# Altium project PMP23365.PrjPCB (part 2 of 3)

## Sheet PMP23365B_SH2.SchDoc: Active Clamp Forward Converter
size 558 x 431 mm; Date: Not shown in title block; ApprovedBy: Not shown in title block; CheckedBy: Not shown in title block; Author: Not shown in title block; CompanyName: Not shown in title block; DrawnBy: D Xing; Engineer: Not shown in title block; Organization: Not shown in title block; Address1: Not shown in title block; Address2: Not shown in title block; Address3: Not shown in title block; Address4: Not shown in title block; DocumentNumber: 1; Revision: Use project parameter SCH_Rev; SheetNumber: 2; SheetTotal: 3; PageSetup: Record=PageOptions¦CenterHorizontal=True¦CenterVertical=True¦PrintScale=1.00¦XCorrection=1.00¦YCorrection=1.00¦PrintKind=0¦BorderSize=5000000¦LeftOffset=0¦BottomOffset=0¦Orientation=2¦PaperLength=1000¦PaperWidth=1000¦Scale=100¦PaperSource=15¦PrintQuality=600¦MediaType=1¦DitherType=10¦PaperKind=Letter¦PrintScaleMode=1
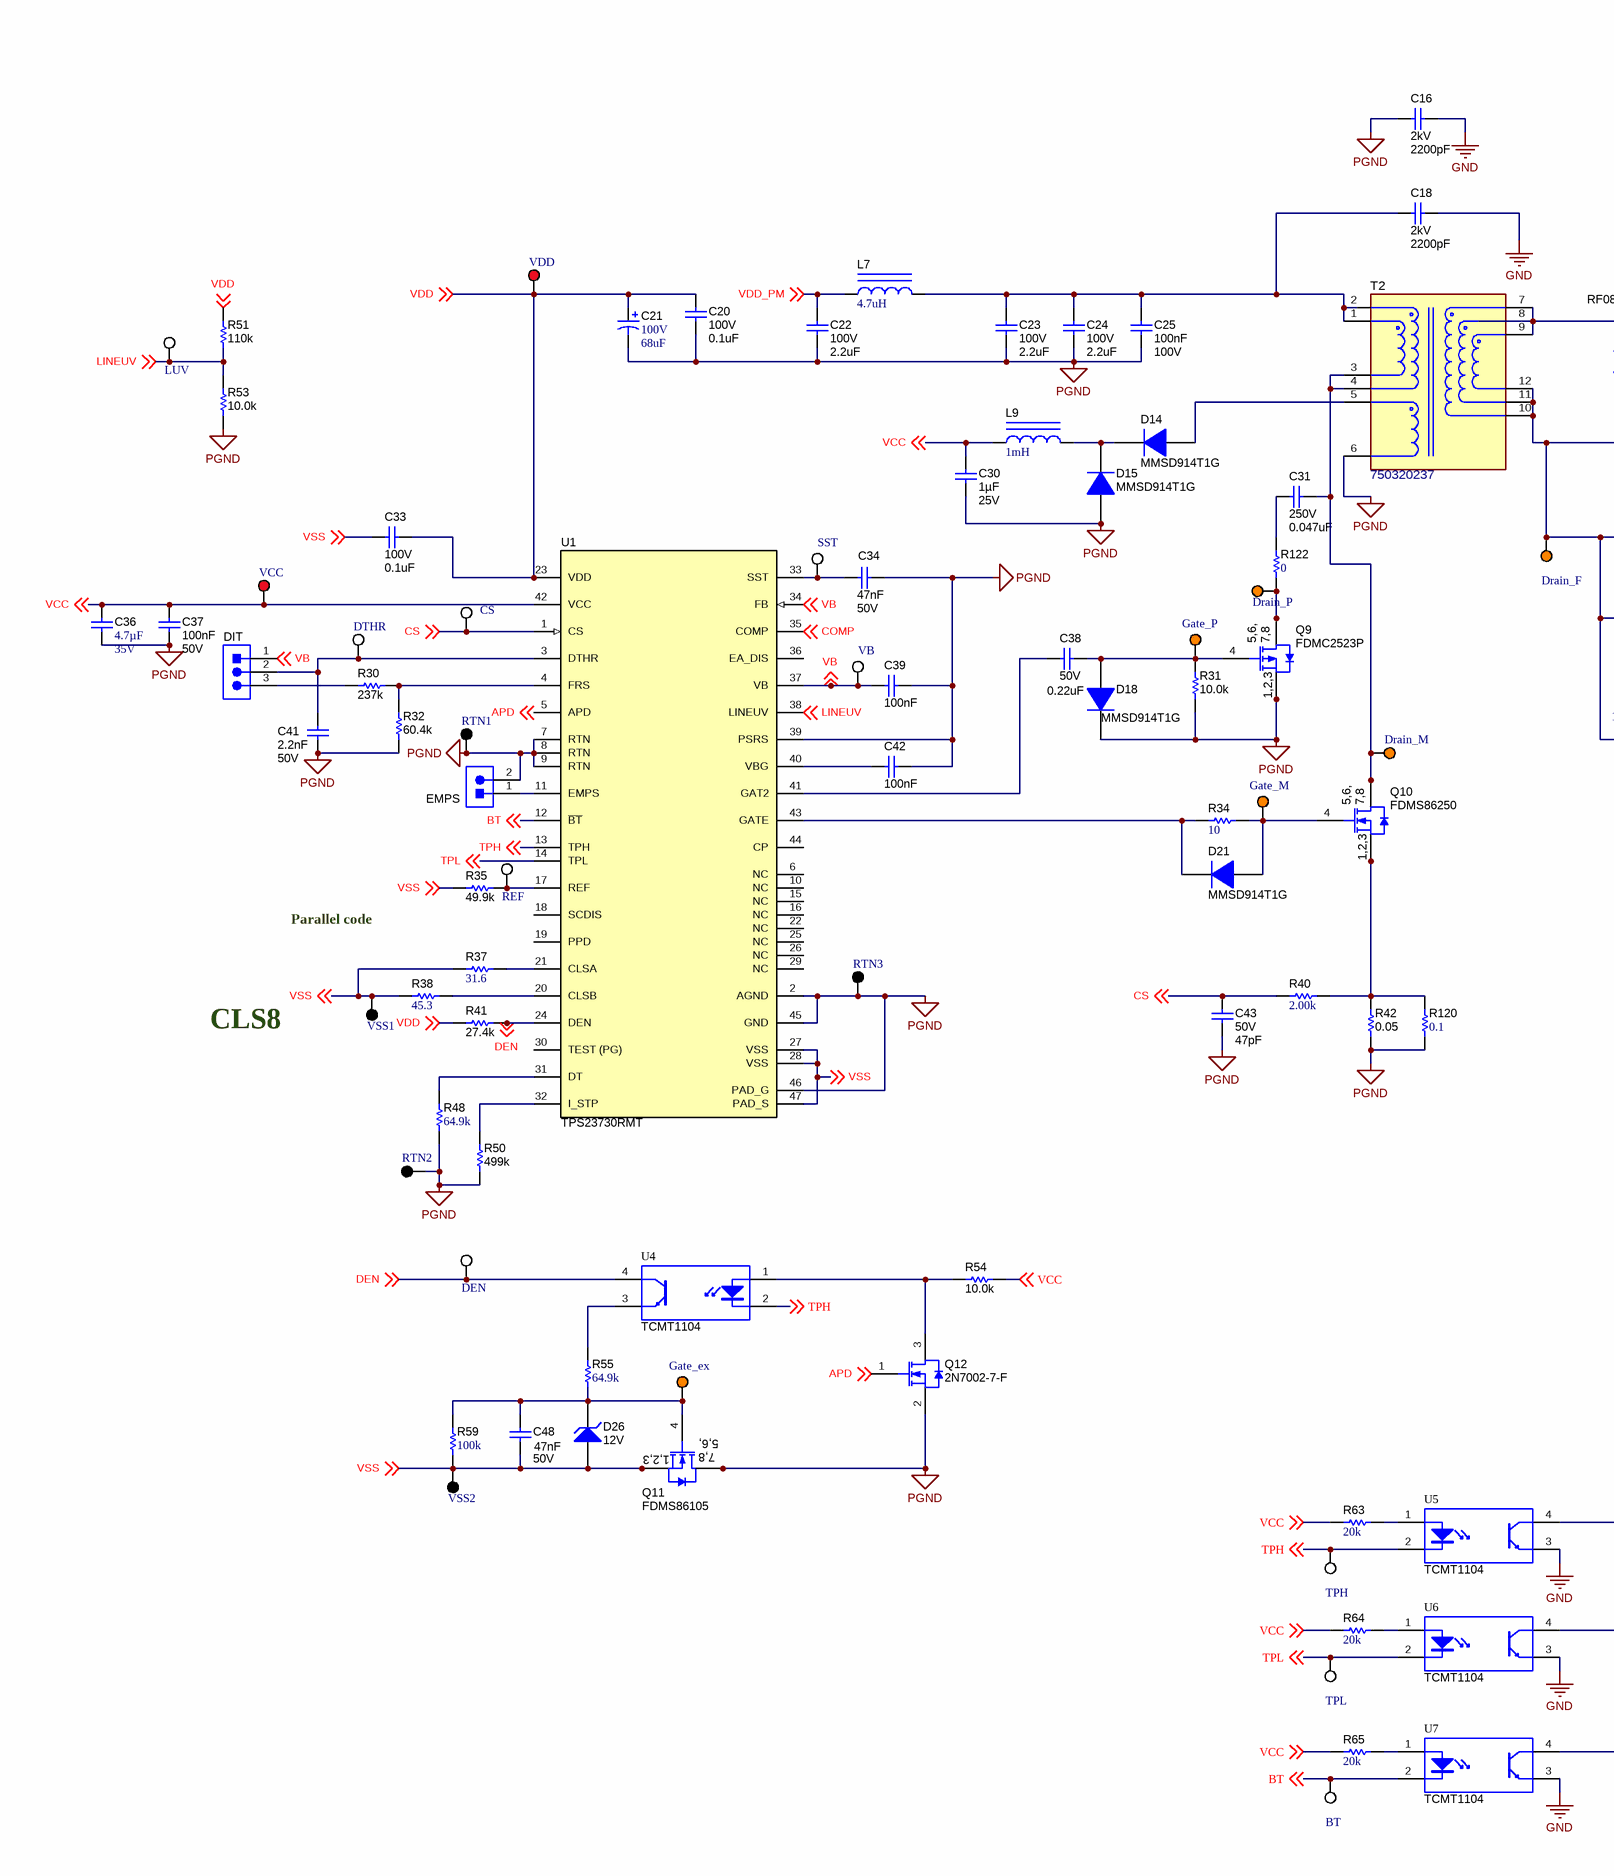
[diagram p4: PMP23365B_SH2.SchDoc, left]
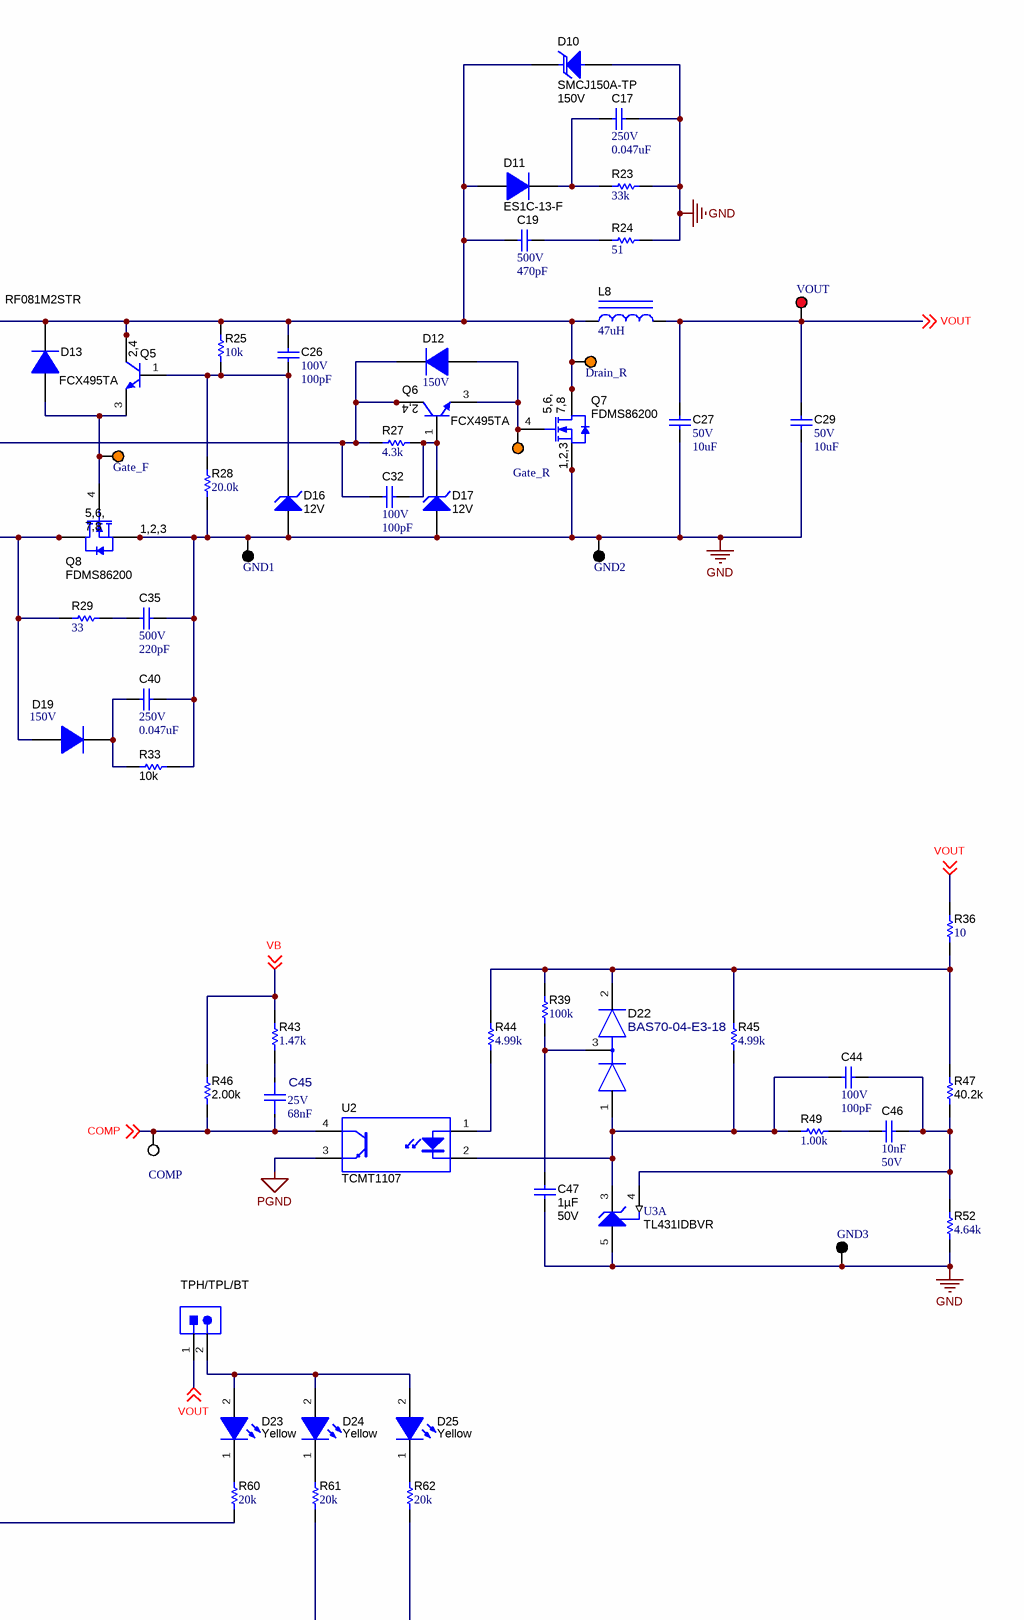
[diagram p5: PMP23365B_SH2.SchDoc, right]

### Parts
BT  5002  [Keystone5002]  (value not drawn)
C16  VDC_V: 2kV  ValueDisplayed: 2200pF  [1812_HV]  (hidden comment: C4532X7R3D222K130KA)
C17  VDC_V: 250V  ValueDisplayed: 0.047uF  [1206_180]  (hidden comment: GRM31CR72E473KW03L)
C18  VDC_V: 2kV  ValueDisplayed: 2200pF  [1812_HV]  (hidden comment: C4532X7R3D222K130KA)
C19  VDC_V: 500V  ValueDisplayed: 470pF  [1206]  (hidden comment: VJ1206Y471KBEAT4X)
C20  VDC_V: 100V  ValueDisplayed: 0.1uF  [1206]  (hidden comment: GRM319R72A104KA01D)
C21  VDC_V: 100V  ValueDisplayed: 68uF  [CAPSMT_62_KE0]  (hidden comment: EMVA101ATR680MKE0S)
C22  VDC_V: 100V  ValueDisplayed: 2.2uF  [1210_270]  (hidden comment: GRM32ER72A225KA35L)
C23  VDC_V: 100V  ValueDisplayed: 2.2uF  [1210_270]  (hidden comment: GRM32ER72A225KA35L)
C24  VDC_V: 100V  ValueDisplayed: 2.2uF  [1210_270]  (hidden comment: GRM32ER72A225KA35L)
C25  Cap_F: 100nF  VDC_V: 100V  [0805_HV]  (hidden comment: GRM21BR72A104KAC4L)
C26  VDC_V: 100V  ValueDisplayed: 100pF  [0603]  (hidden comment: GCM1885C2A101JA16D)
C27  VDC_V: 50V  ValueDisplayed: 10uF  [1210_270]  (hidden comment: GRM32ER61H106KA12L)
C29  VDC_V: 50V  ValueDisplayed: 10uF  [1210_270]  (hidden comment: GRM32ER61H106KA12L)
C30  Cap_F: 1µF  VDC_V: 25V  [0805_HV]  (hidden comment: GRM21BR71E105KA99L)
C31  VDC_V: 250V  ValueDisplayed: 0.047uF  [1206_180]  (hidden comment: GRM31CR72E473KW03L)
C32  VDC_V: 100V  ValueDisplayed: 100pF  [0603]  (hidden comment: GCM1885C2A101JA16D)
C33  VDC_V: 100V  ValueDisplayed: 0.1uF  [1206]  (hidden comment: GRM319R72A104KA01D)
C34  Cap_F: 47nF  VDC_V: 50V  [0603]  (hidden comment: GRM188R71H473KA61D)
C35  VDC_V: 500V  ValueDisplayed: 220pF  [1206]  (hidden comment: VJ1206Y221KXEAT5Z)
C36  Cap_F: 4.7µF  VDC_V: 35V  [0805_HV]  (hidden comment: C2012X7R1V475K125AC)
C37  Cap_F: 100nF  VDC_V: 50V  [0805_HV]  (hidden comment: GCM21BR71H104KA37K)
C38  VDC_V: 50V  ValueDisplayed: 0.22uF  [0805_HV]  (hidden comment: C2012X5R1H224K125AA)
C39  Cap_F: 100nF  [0603]  (hidden comment: CGA3E2X7R1E104K080AA)
C40  VDC_V: 250V  ValueDisplayed: 0.047uF  [1206_180]  (hidden comment: GRM31CR72E473KW03L)
C41  Cap_F: 2.2nF  VDC_V: 50V  [0603]  (hidden comment: C0603C222K5RAC)
C42  Cap_F: 100nF  [0603]  (hidden comment: CGA3E2X7R1E104K080AA)
C43  VDC_V: 50V  ValueDisplayed: 47pF  [0603]  (hidden comment: GRM1885C1H470JA01D)
C44  VDC_V: 100V  ValueDisplayed: 100pF  [0603]  (hidden comment: GCM1885C2A101JA16D)
C45  VDC_V: 25V  ValueDisplayed: 68nF  [FP-C1608X8R1E683M080AA_0603-MFG]  (hidden comment: C1608X8R1E683M080AA)
C46  Cap_F: 10nF  VDC_V: 50V  [0603]  (hidden comment: C0603X103K5RACTU)
C47  Cap_F: 1µF  VDC_V: 50V  [0805_HV]  (hidden comment: C2012X7R1H105K125AB)
C48  Cap_F: 47nF  VDC_V: 50V  [0603]  (hidden comment: GRM188R71H473KA61D)
COMP  5002  [Keystone5002]  (value not drawn)
CS  5002  [Keystone5002]  (value not drawn)
D10  SMCJ150A-TP  value 150V  [SMC]
D11  ES1C-13-F  [SMA]
D12  value 150V  [SMA]  (hidden comment: ES1C-13-F)
D13  RF081M2STR  [SOD-123]
D14  MMSD914T1G  [SOD-123]
D15  MMSD914T1G  [SOD-123]
D16  value 12V  [SOD-123]  (hidden comment: MMSZ5242B-7-F)
D17  value 12V  [SOD-123]  (hidden comment: MMSZ5242B-7-F)
D18  MMSD914T1G  [SOD-123]
D19  value 150V  [SMA]  (hidden comment: ES1C-13-F)
D21  MMSD914T1G  [SOD-123]
D22  BAS70-04-E3-18  [FP-BAS70-04-E3-18_SOT23-3-MFG]
D23  value Yellow  [WL-SMCW_YELLOW]  (hidden comment: 150060YS75000)
D24  value Yellow  [WL-SMCW_YELLOW]  (hidden comment: 150060YS75000)
D25  value Yellow  [WL-SMCW_YELLOW]  (hidden comment: 150060YS75000)
D26  value 12V  [SOD-123]  (hidden comment: MMSZ5242B-7-F)
DEN  5002  [Keystone5002]  (value not drawn)
DIT  5-146278-3  [TE_5-146278-3]  (value not drawn)
Drain_F  5003  [Keystone5003]  (value not drawn)
Drain_M  5003  [Keystone5003]  (value not drawn)
Drain_P  5003  [Keystone5003]  (value not drawn)
Drain_R  5003  [Keystone5003]  (value not drawn)
DTHR  5002  [Keystone5002]  (value not drawn)
EMPS  5-146278-2  [TE_5-146278-2]  (value not drawn)
Gate_ex  5003  [Keystone5003]  (value not drawn)
Gate_F  5003  [Keystone5003]  (value not drawn)
Gate_M  5003  [Keystone5003]  (value not drawn)
Gate_P  5003  [Keystone5003]  (value not drawn)
Gate_R  5003  [Keystone5003]  (value not drawn)
GND1  5001  [Keystone5001]  (value not drawn)
GND2  5001  [Keystone5001]  (value not drawn)
GND3  5001  [Keystone5001]  (value not drawn)
L7  ValueDisplayed: 4.7uH  [IND_PIMB065T]  (hidden comment: PIMB065T-4R7)
L8  ValueDisplayed: 47uH  [WE-HCB_1890]  (hidden comment: 74435574700)
L9  ValueDisplayed: 1mH  [DO1608C]  (hidden comment: DO1608C-105MLB)
LUV  5002  [Keystone5002]  (value not drawn)
Q5  FCX495TA  [SOT-89-3]
Q6  FCX495TA  [SOT-89-3]
Q7  FDMS86200  [TRANS_Fairchild_PQFN08A]
Q8  FDMS86200  [TRANS_Fairchild_PQFN08A]
Q9  FDMC2523P  [MLP08S]
Q10  FDMS86250  [TRANS_Fairchild_PQFN08A]
Q11  FDMS86105  [PowerPAK_SO-8_NoVias]
Q12  2N7002-7-F  [SOT-23]
R23  ValueDisplayed: 33k  [2512]  (hidden comment: CRCW251233K0JNEG)
R24  ValueDisplayed: 51  [2512]  (hidden comment: CRCW251251R0JNEG)
R25  ValueDisplayed: 10k  [1206]  (hidden comment: CRCW120610K0JNEA)
R27  ValueDisplayed: 4.3k  [1206]  (hidden comment: CRCW12064K30JNEA)
R28  ValueDisplayed: 20.0k  [1206]  (hidden comment: CRCW120620K0FKEA)
R29  ValueDisplayed: 33  [1206]  (hidden comment: CRCW120633R0JNEA)
R30  ValueDisplayed: 237k  [0603]  (hidden comment: RC0603FR-07237KL)
R31  ValueDisplayed: 10.0k  [0603]  (hidden comment: CRCW060310K0FKEA)
R32  ValueDisplayed: 60.4k  [0603]  (hidden comment: CRCW060360K4FKEA)
R33  ValueDisplayed: 10k  [2512]  (hidden comment: CRCW251210K0JNEG)
R34  ValueDisplayed: 10  [0603]  (hidden comment: CRCW060310R0JNEA)
R35  ValueDisplayed: 49.9k  [0603]  (hidden comment: CRCW060349K9FKEA)
R36  ValueDisplayed: 10  [0603]  (hidden comment: CRCW060310R0JNEA)
R37  ValueDisplayed: 31.6  [0603]  (hidden comment: RC0603FR-0731R6L)
R38  ValueDisplayed: 45.3  [0603]  (hidden comment: RC0603FR-0745R3L)
R39  ValueDisplayed: 100k  [0603]  (hidden comment: CRCW0603100KJNEAC)
R40  ValueDisplayed: 2.00k  [0603]  (hidden comment: RC0603FR-072KL)
R41  ValueDisplayed: 27.4k  [0603]  (hidden comment: RC0603FR-0727K4L)
R42  ValueDisplayed: 0.05  [1206]  (hidden comment: ERJ-8CWFR050V)
R43  ValueDisplayed: 1.47k  [0603]  (hidden comment: RC0603FR-071K47L)
R44  ValueDisplayed: 4.99k  [0603]  (hidden comment: CRCW06034K99FKEA)
R45  ValueDisplayed: 4.99k  [0603]  (hidden comment: CRCW06034K99FKEA)
R46  ValueDisplayed: 2.00k  [0603]  (hidden comment: CRCW06032K00FKEA)
R47  ValueDisplayed: 40.2k  [0603]  (hidden comment: CRCW060340K2FKEA)
R48  ValueDisplayed: 64.9k  [0603]  (hidden comment: CRCW060364K9FKEA)
R49  ValueDisplayed: 1.00k  [0603]  (hidden comment: CRCW06031K00FKEA)
R50  ValueDisplayed: 499k  [0603]  (hidden comment: CRCW0603499KFKEA)
R51  ValueDisplayed: 110k  [0603]  (hidden comment: CRCW0603110KFKEA)
R52  ValueDisplayed: 4.64k  [0603]  (hidden comment: RC0603FR-074K64L)
R53  ValueDisplayed: 10.0k  [0603]  (hidden comment: CRCW060310K0FKEA)
R54  ValueDisplayed: 10.0k  [0603L]  (hidden comment: CRCW060310K0FKEA)
R55  ValueDisplayed: 64.9k  [0603]  (hidden comment: CRCW060364K9FKEA)
R59  ValueDisplayed: 100k  [0603]  (hidden comment: CRCW0603100KFKEA)
R60  ValueDisplayed: 20k  [0603]  (hidden comment: CRCW060320K0JNEA)
R61  ValueDisplayed: 20k  [0603]  (hidden comment: CRCW060320K0JNEA)
R62  ValueDisplayed: 20k  [0603]  (hidden comment: CRCW060320K0JNEA)
R63  ValueDisplayed: 20k  [0603]  (hidden comment: CRCW060320K0JNEA)
R64  ValueDisplayed: 20k  [0603]  (hidden comment: CRCW060320K0JNEA)
R65  ValueDisplayed: 20k  [0603]  (hidden comment: CRCW060320K0JNEA)
R120  ValueDisplayed: 0.1  [1206]  (hidden comment: CRM1206-FX-R100ELF)
R122  ValueDisplayed: 0  [0805_HV]  (hidden comment: MCR10EZPJ000)
REF  5002  [Keystone5002]  (value not drawn)
RTN1  5001  [Keystone5001]  (value not drawn)
RTN2  5001  [Keystone5001]  (value not drawn)
RTN3  5001  [Keystone5001]  (value not drawn)
SST  5002  [Keystone5002]  (value not drawn)
T2  750320237  [FP-750320237_SMT12_29MM65_21MM8-MFG]
TPH  5002  [Keystone5002]  (value not drawn)
TPH/TPL/BT  5-146278-2  [TE_5-146278-2]  (value not drawn)
TPL  5002  [Keystone5002]  (value not drawn)
U1  TPS23730RMT  [RMT0045A]
U2  TCMT1107  [SOP-4]
U3  TL431IDBVR  [DBV0005A_M]  (part A of 2)
U4  TCMT1104  [SOP-4]
U5  TCMT1104  [SOP-4]
U6  TCMT1104  [SOP-4]
U7  TCMT1104  [SOP-4]
VB  5002  [Keystone5002]  (value not drawn)
VCC  5000  [Keystone5000]  (value not drawn)
VDD  5000  [Keystone5000]  (value not drawn)
VOUT  5000  [Keystone5000]  (value not drawn)
VSS1  5001  [Keystone5001]  (value not drawn)
VSS2  5001  [Keystone5001]  (value not drawn)

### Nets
GND: C16.1 C17.1 C18.1 C27.2 C29.2 C35.1 C40.1 C47.2 D10.2(A) D16.2(A) D17.2(A) GND1.1 GND2.1 GND3.1 Q7.1(S) Q7.2(S) Q7.3(S) Q8.1(S) Q8.2(S) Q8.3(S) R23.2 R24.2 R28.1 R33.2 R52.1 U3.5(ANODE) U5.3(E) U6.3(E) U7.3(E)
PGND: C16.2 C20.2 C21.2(-) C22.2 C23.2 C24.2 C25.2 C30.2 C34.1 C36.2 C37.2 C39.1 C41.2 C42.1 C43.2 D15.2(A) D18.1(K) EMPS.2 Q9.1(S) Q9.2(S) Q9.3(S) Q11.5(D) Q11.6(D) Q11.7(D) Q11.8(D) Q11.9(D) Q12.2(S) R31.1 R32.1 R42.1 R48.2 R50.1 R53.1 R120.1 RTN1.1 RTN2.1 RTN3.1 T2.6 U1.2(AGND) U1.7(RTN) U1.8(RTN) U1.9(RTN) U1.39(PSRS) U1.45(GND) U1.46(PAD_G) U2.3(E)
APD: Q12.1(G) U1.5(APD) ; off-sheet APD
BT: BT.1 U1.12(~{BT}) U7.2(K) ; off-sheet BT
COMP: C45.1 COMP.1 R46.1 U1.35(COMP) U2.4(C) ; off-sheet COMP
CS: C43.1 CS.1 R40.1 U1.1(CS) ; off-sheet CS
DEN: DEN.1 R41.2 U1.24(DEN) U4.4(C) ; off-sheet DEN
LINEUV: LUV.1 R51.1 R53.2 U1.38(LINEUV) ; off-sheet LINEUV
TPH: TPH.1 U1.13(TPH) U4.2(K) U5.2(K) ; off-sheet TPH
TPL: TPL.1 U1.14(TPL) U6.2(K) ; off-sheet TPL
VB: C39.2 DIT.1 R43.2 R46.2 U1.34(FB) U1.37(VB) VB.1 ; off-sheet VB
VCC: C30.1 C36.1 C37.1 L9.1 R54.2 R63.2 R64.2 R65.2 U1.42(VCC) VCC.1 ; off-sheet VCC
VDD: C20.1 C21.1(+) C33.1 R41.1 R51.2 U1.23(VDD) VDD.1 ; off-sheet VDD
VDD_PM: C22.1 L7.1 ; off-sheet VDD_PM
VOUT: C27.1 C29.1 L8.2 R36.2 TPH/TPL/BT.1 VOUT.1 ; off-sheet VOUT
VSS: C33.2 C48.2 D26.2(A) Q11.1(S) Q11.2(S) Q11.3(S) R35.1 R37.1 R38.1 R59.1 U1.27(VSS) U1.28(VSS) U1.47(PAD_S) VSS1.1 VSS2.1 ; off-sheet VSS
NetC17_2: C17.2 D11.1(K) R23.1
NetC18_2: C18.2 C23.1 C24.1 C25.1 L7.2 T2.1 T2.2
NetC19_1: C19.1 R24.1
NetC19_2: C19.2 C26.2 D10.1(K) D11.2(A) D13.1(K) Drain_R.1 L8.1 Q5.2(C) Q5.4(C) Q7.5(D) Q7.6(D) Q7.7(D) Q7.8(D) R25.2 T2.7 T2.8 T2.9
NetC26_1: C26.1 D16.1(K) Q5.1(B) R25.1 R28.2
NetC31_1: C31.1 Drain_M.1 Q10.5(D) Q10.6(D) Q10.7(D) Q10.8(D) T2.3 T2.4
NetC31_2: C31.2 R122.2
NetC32_1: C32.1 D17.1(K) Q6.1(B) R27.1
NetC32_2: C32.2 D12.1(K) D19.2(A) Drain_F.1 Q6.2(C) Q6.4(C) Q8.5(D) Q8.6(D) Q8.7(D) Q8.8(D) R27.2 R29.1 T2.10 T2.11 T2.12
NetC34_2: C34.2 SST.1 U1.33(SST)
NetC35_2: C35.2 R29.2
NetC38_1: C38.1 D18.2(A) Gate_P.1 Q9.4(G) R31.2
NetC38_2: C38.2 U1.41(GAT2)
NetC40_2: C40.2 D19.1(K) R33.1
NetC41_1: C41.1 DIT.2 DTHR.1 U1.3(DTHR)
NetC42_2: C42.2 U1.40(VBG)
NetC44_1: C44.1 C46.1 R47.2 R52.2 U3.4(REF)
NetC44_2: C44.2 D22.1(1_ANODE) R45.1 R49.1 U2.2(K) U3.3(CATHODE)
NetC45_2: C45.2 R43.1
NetC46_2: C46.2 R49.2
NetC47_1: C47.1 D22.3(1_CATHODE/2_ANODE) R39.1
NetC48_1: C48.1 D26.1(K) Gate_ex.1 Q11.4(G) R55.2 R59.2
NetD12_2: D12.2(A) Gate_R.1 Q6.3(E) Q7.4(G)
NetD13_2: D13.2(A) Gate_F.1 Q5.3(E) Q8.4(G)
NetD14_1: D14.1(K) D15.1(K) L9.2
NetD14_2: D14.2(A) T2.5
NetD21_1: D21.1(K) R34.1 U1.43(GATE)
NetD21_2: D21.2(A) Gate_M.1 Q10.4(G) R34.2
NetD22_2: D22.2(2_CATHODE) R36.1 R39.2 R44.2 R45.2 R47.1
NetD23_1: D23.1(K) R60.2
NetD23_2: D23.2(A) D24.2(A) D25.2(A) TPH/TPL/BT.2
NetD24_1: D24.1(K) R61.2
NetD25_1: D25.1(K) R62.2
NetDIT_3: DIT.3 R30.1
NetDrain_P_1: Drain_P.1 Q9.5(D) Q9.6(D) Q9.7(D) Q9.8(D) R122.1
NetEMPS_1: EMPS.1 U1.11(EMPS)
NetQ10_1: Q10.1(S) Q10.2(S) Q10.3(S) R40.2 R42.2 R120.2
NetQ12_3: Q12.3(D) R54.1 U4.1(A)
NetR30_2: R30.2 R32.2 U1.4(FRS)
NetR35_2: R35.2 REF.1 U1.17(REF)
NetR37_2: R37.2 U1.21(CLSA)
NetR38_2: R38.2 U1.20(CLSB)
NetR44_1: R44.1 U2.1(A)
NetR48_1: R48.1 U1.31(DT)
NetR50_2: R50.2 U1.32(I_STP)
NetR55_1: R55.1 U4.3(E)
NetR60_1: R60.1 U5.4(C)
NetR61_1: R61.1 U6.4(C)
NetR62_1: R62.1 U7.4(C)
NetR63_1: R63.1 U5.1(A)
NetR64_1: R64.1 U6.1(A)
NetR65_1: R65.1 U7.1(A)

Not connected (* = marked no-connect by the designer): U1 6(NC) 10(NC) 15(NC) 16(NC) 18(SCDIS) 19(PPD) 22(NC) 25(NC) 26(NC) 29(NC) 30(TEST_(PG)) 36(EA_DIS) 44(CP)

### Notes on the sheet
- Parallel code
- CLS8

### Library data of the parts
BT DEN LUV REF TPH TPL = CMP-0055139-1: Test Point, Miniature, White, TH; Manufacturer: Keystone; CNHeader: FALSE; Green_Lifecycle: Active; Green_REACh: Passed; ContactFinish: Silver; CT: TRUE
C16 C18 = CMP-0009358-2: CAP, CERM, 2200 pF, 2000 V, +/- 10%, X7R, 1812; Manufacturer: TDK; TaMin_C: -55°C; Polarized: N; SizeAreaWB_mm2: 23.1; Value1: Unknown; U/M: EA; Value: 2200pF; TaMax_C: 125°C; SizeZ_mm: 1.35; SizeX_mm: 4.5; SizeY_mm: 3.2; Cap_Case: 1812; Value2: 2000V; SizeArea_mm2: 14.4; Cap_F: 2.2nF; AEC Category: Q200
C17 C31 C40 = CMP-0008975-2: CAP, CERM, 0.047 uF, 250 V, +/- 10%, X7R, 1206; Manufacturer: MuRata; TaMin_C: -55°C; Polarized: N; SizeAreaWB_mm2: 10.92; Value1: Unknown; U/M: EA; TaMax_C: 125°C; SizeZ_mm: 1.8; SizeX_mm: 3.2; SizeY_mm: 1.6; Cap_Case: 1206; SizeArea_mm2: 5.12; Cap_F: 47nF; AEC Category: Q200
C19 = CMP-0009053-2: CAP, CERM, 470 pF, 500 V, +/- 10%, X7R, 1206; Manufacturer: Vishay-Vitramon; TaMin_C: -55°C; Polarized: N; SizeAreaWB_mm2: 10.92; Value1: Unknown; U/M: EA; Value: 470pF; TaMax_C: 125°C; SizeZ_mm: 1.35; SizeX_mm: 3.2; SizeY_mm: 1.6; SizeArea_mm2: 5.12; AEC Category: Q200
C20 C33 = CMP-0008881-2: CAP, CERM, 0.1 uF, 100 V, +/- 10%, X7R, 1206; Manufacturer: MuRata; TaMin_C: -55°C; Polarized: N; SizeAreaWB_mm2: 10.92; Value1: Unknown; U/M: EA; Value: 0.1uF; TaMax_C: 125°C; SizeZ_mm: 1.35; SizeX_mm: 3.2; SizeY_mm: 1.6; SizeArea_mm2: 5.12; Cap_F: 100nF; AEC Category: Q200
C21 = CMP-0011231-3: CAP, AL, 68 uF, 100 V, +/- 20%, SMD; Manufacturer: Chemi-Con; TaMin_C: -40°C; Polarized: Y; SizeAreaWB_mm2: 225; Value1: Unknown; U/M: EA; Value: 68uF; TaMax_C: 85°C; SizeZ_mm: 13.5; SizeX_mm: 13; Cap_Case: KE0; SizeArea_mm2: 169; CompType: Capacitor; Cap_F: 68µF; IRMS_A: 380mA; AEC Category: Q200
C22-C24 = CMP-0009232-2: CAP, CERM, 2.2 uF, 100 V, +/- 10%, X7R, 1210; Manufacturer: MuRata; TaMin_C: -55°C; ESR_ohm: 7m; Polarized: N; SizeAreaWB_mm2: 14.7; Value1: 0.007 ohm; U/M: EA; Value: 2.2uF; TaMax_C: 125°C; SizeZ_mm: 2.7; SizeX_mm: 3.2; SizeY_mm: 2.5; Cap_Case: 1210; SizeArea_mm2: 8; Cap_F: 2.2µF; IRMS_A: 4.4A; AEC Category: Q200
C25 = CMP-0008363-2: CAP, CERM, 0.1 uF, 100 V, +/- 10%, X7R, 0805; Manufacturer: MuRata; TaMin_C: -55°C; Polarized: N; SizeAreaWB_mm2: 6.75; Value1: Unknown; U/M: EA; Value: 0.1uF; TaMax_C: 125°C; SizeZ_mm: 1.45; SizeX_mm: 2; SizeY_mm: 1.25; Cap_Case: 0805; SizeArea_mm2: 2.5; AEC Category: Q200
C26 C32 C44 = CMP-0007130-4: CAP, CERM, 100 pF, 100 V, +/- 5%, C0G/NP0, AEC-Q200 Grade 1, 0603; Manufacturer: MuRata; TaMin_C: -55°C; Polarized: N; SizeAreaWB_mm2: 4.68; Value1: Unknown; U/M: EA; TaMax_C: 125°C; SizeZ_mm: 1; SizeX_mm: 1.6; SizeY_mm: 0.8; SizeArea_mm2: 1.28; AEC Qualified: Y; AEC Category: Q200; Value: 100pF
C27 C29 = CMP-0009214-2: CAP, CERM, 10 uF, 50 V, +/- 10%, X5R, 1210; Manufacturer: MuRata; TaMin_C: -55°C; Polarized: N; SizeAreaWB_mm2: 14.7; Value1: Unknown; U/M: EA; Value: 10uF; TaMax_C: 85°C; SizeZ_mm: 2.7; SizeX_mm: 3.2; SizeY_mm: 2.5; Cap_Case: 1210; SizeArea_mm2: 8; Cap_F: 10µF; AEC Category: Q200
C30 = CMP-0008336-2: CAP, CERM, 1 uF, 25 V, +/- 10%, X7R, 0805; Manufacturer: MuRata; TaMin_C: -55°C; Polarized: N; SizeAreaWB_mm2: 6.75; Value1: Unknown; U/M: EA; Value: 1uF; TaMax_C: 125°C; SizeZ_mm: 1.45; SizeX_mm: 2; SizeY_mm: 1.25; Cap_Case: 0805; SizeArea_mm2: 2.5; AEC Category: Q200
C34 C48 = CMP-0007457-4: CAP, CERM, 0.047 uF, 50 V, +/- 10%, X7R, 0603; Manufacturer: MuRata; TaMin_C: -55°C; Polarized: N; SizeAreaWB_mm2: 4.68; Value1: Unknown; U/M: EA; TaMax_C: 125°C; SizeZ_mm: 1; SizeX_mm: 1.6; SizeY_mm: 0.8; SizeArea_mm2: 1.28; AEC Category: Q200
C35 = CMP-0009046-1: CAP, CERM, 220 pF, 500 V, +/- 10%, X7R, 1206; Manufacturer: Vishay-Vitramon; TaMin_C: -55°C; Polarized: N; SizeAreaWB_mm2: 10.92; Value1: Unknown; U/M: EA; Value: 220pF; TaMax_C: 125°C; SizeZ_mm: 1.35; SizeX_mm: 3.2; SizeY_mm: 1.6; SizeArea_mm2: 5.12; AEC Category: Q200
C36 = CMP-0007885-1: CAP, CERM, 4.7 uF, 35 V, +/- 10%, X7R, 0805; Manufacturer: TDK; TaMin_C: -55°C; ESR_ohm: 2.346m; Polarized: N; SizeAreaWB_mm2: 6.75; Value1: 0.002346 ohm; U/M: EA; Value: 4.7uF; TaMax_C: 125°C; SizeZ_mm: 1.45; SizeX_mm: 2; SizeY_mm: 1.25; Cap_Case: 0805; SizeArea_mm2: 2.5; IRMS_A: 4.2602A; AEC Category: Q200
C37 = CMP-0008021-2: CAP, CERM, 0.1 uF, 50 V, +/- 10%, X7R, AEC-Q200 Grade 1, 0805; Manufacturer: MuRata; TaMin_C: -55°C; Polarized: N; SizeAreaWB_mm2: 6.75; Value1: Unknown; U/M: EA; Value: 0.1uF; TaMax_C: 125°C; SizeZ_mm: 1.45; SizeX_mm: 2; SizeY_mm: 1.25; Cap_Case: 0805; SizeArea_mm2: 2.5; AEC Qualified: Y; AEC Grade: 1; AEC Category: Q200
C38 = CMP-0007835-2: CAP, CERM, 0.22 uF, 50 V, +/- 10%, X5R, 0805; Manufacturer: TDK; TaMin_C: -55°C; ESR_ohm: 0.016949; Polarized: N; SizeAreaWB_mm2: 6.75; Value1: 0.016949 ohm; U/M: EA; Value: 0.22uF; TaMax_C: 85°C; SizeZ_mm: 1.45; SizeX_mm: 2; Cap_Case: 0805; SizeArea_mm2: 2.5; Cap_F: 220nF; SizeY_mm: 1.25; IRMS_A: 1.59611A; AEC Category: Q200
C39 C42 = CMP-0007077-5: CAP, CERM, 0.1 uF, 25 V, +/- 10%, X7R, AEC-Q200 Grade 1, 0603; Manufacturer: TDK; TaMin_C: -55°C; Polarized: N; SizeAreaWB_mm2: 4.68; Value1: Unknown; U/M: EA; Value: 0.1uF; TaMax_C: 125°C; SizeZ_mm: 1; SizeX_mm: 1.6; SizeY_mm: 0.8; Value2: 25V; SizeArea_mm2: 1.28; AEC Qualified: Y; AEC Category: Q200
C41 = CMP-0006897-4: CAP, CERM, 2200 pF, 50 V, +/- 10%, X7R, 0603; Manufacturer: Kemet; TaMin_C: -55°C; Polarized: N; SizeAreaWB_mm2: 4.68; Value1: Unknown; U/M: EA; Value: 2200pF; TaMax_C: 125°C; SizeZ_mm: 1; SizeX_mm: 1.6; SizeY_mm: 0.8; SizeArea_mm2: 1.28; AEC Category: Q200
C43 = CMP-0007220-4: CAP, CERM, 47 pF, 50 V, +/- 5%, C0G/NP0, 0603; Manufacturer: MuRata; TaMin_C: -55°C; Polarized: N; SizeAreaWB_mm2: 4.68; Value1: Unknown; U/M: EA; Value: 47pF; TaMax_C: 125°C; SizeZ_mm: 1; SizeX_mm: 1.6; SizeY_mm: 0.8; SizeArea_mm2: 1.28; AEC Category: Q200
C45 = CMP-0094554-1: Multilayer Ceramic Capacitors 68nF ±20% 25V X8R SMD 0603; Manufacturer: TDK; TempCo: 0.15; AEC Qualified: No; Tolerance_%: 0.2%; Voltage: 50V; SizeZ_mm: 0.9mm
C46 = CMP-0006978-4: CAP, CERM, 0.01 uF, 50 V, +/- 10%, X7R, 0603; Manufacturer: Kemet; TaMin_C: -55°C; Polarized: N; SizeAreaWB_mm2: 4.68; Value1: Unknown; U/M: EA; Value: 0.01uF; TaMax_C: 125°C; SizeZ_mm: 1; SizeX_mm: 1.6; SizeY_mm: 0.8; SizeArea_mm2: 1.28; AEC Category: Q200
C47 = CMP-0007873-2: CAP, CERM, 1 uF, 50 V, +/- 10%, X7R, 0805; Manufacturer: TDK; TaMin_C: -55°C; ESR_ohm: 8.782m; Polarized: N; SizeAreaWB_mm2: 6.75; Value1: 0.008782 ohm; U/M: EA; Value: 1uF; TaMax_C: 125°C; SizeZ_mm: 1.45; SizeX_mm: 2; SizeY_mm: 1.25; Cap_Case: 0805; SizeArea_mm2: 2.5; IRMS_A: 2.20488A; AEC Category: Q200
COMP CS DTHR SST VB = CMP-0055139-2: Test Point, Miniature, White, TH; Manufacturer: Keystone Electronics; ContactFinish: Silver; Green_REACh: Passed; CT: TRUE; Green_Lifecycle: Active; CNHeader: FALSE
D10 = CMP-0005708-3: Diode, TVS, Uni, 150 V, 243 Vc, SMC; Manufacturer: Micro Commercial Components; SizeX_mm: 8.13; Vc: 243V; AEC Category: Q101; SizeY_mm: 6.22; SizeAreaWB_mm2: 83.2686; SizeZ_mm: 2.6; Ppk: 1.5kW; AEC Qualified: N; Ipp: 6.2A; Value1: 1500W; Vbr_Max: 185V; SizeArea_mm2: 50.5686; Vbr_Min: 167V
D11 = CMP-0029023-2: Diode, Superfast Rectifier, 150 V, 1 A, SMA; Manufacturer: Diodes Inc.; TJmax_C: 150°C; Vr_V: 150V; Value2: 0.92V; SizeX_mm: 5.59; Green_REACh: Incomplete; SizeAreaWB_mm2: 37.3428; Value: 150V; Vf_V: 920mV; Green_Lifecycle: Not Set; Value1: 1A; SizeZ_mm: 2.87; SizeArea_mm2: 16.3228; SizeY_mm: 2.92; AEC Category: Q101; RJC_CperW: 25
D12 D19 = CMP-0029023-2: Diode, Superfast Rectifier, 150 V, 1 A, SMA; Manufacturer: Diodes Inc.; SizeX_mm: 5.59; RJC_CperW: 25; Vf_V: 920mV; TJmax_C: 150°C; SizeAreaWB_mm2: 37.3428; Io_A: 1A; Green_REACh: Incomplete; SizeY_mm: 2.92; Green_Lifecycle: Not Set; SizeArea_mm2: 16.3228; AEC Category: Q101; SizeZ_mm: 2.87; Value2: 0.92V
D13 = CMP-0076993-2: Diode, Fast Rectifier, 200 V, 0.8 A, SOD-123; Manufacturer: Rohm; Value: 200V; AEC Category: Q101; SizeAreaWB_mm2: 13.095; Value1: 0.8A; SizeY_mm: 1.7; SizeZ_mm: 1.35; Green_REACh: Incomplete; Green_Lifecycle: Not Set; Io_A: 800mA; SizeX_mm: 3.85; SizeArea_mm2: 6.545; TJmax_C: 150°C; Vf_V: 950mV; Value2: 0.95V
D14 D15 D18 D21 = CMP-0076981-2: Diode, Switching, 100 V, 0.2 A, SOD-123; Manufacturer: ON Semiconductor; Value1: 0.2A; Io_A: 200mA; TJmax_C: 150°C; Green_REACh: Incomplete; SizeY_mm: 1.7; Green_Lifecycle: Not Set; Vr_V: 100V; Value: 100V; SizeZ_mm: 1.35; AEC Category: Q101; SizeAreaWB_mm2: 13.095; SizeX_mm: 3.85; SizeArea_mm2: 6.545
D16 D17 D26 = CMP-0005751-4: Diode, Zener, 12 V, 500 mW, SOD-123; Manufacturer: Diodes Inc.; RJA_CperW: 350; SizeZ_mm: 1.35; SizeAreaWB_mm2: 13.095; AEC Category: Q101; SizeArea_mm2: 6.545; Power_W: 500mW; Value1: 0.5W; SizeY_mm: 1.7; SizeX_mm: 3.85
D22 = CMP-0096356-1: Diode Array 1 Pair Series Connection Schottky 70 V 200mA (DC) Surface Mount TO-236-3, SC-59, SOT-23-3; Manufacturer: Vishay; ValueDisplayed: 1.5pF; Vf_V: 70V; TJmax_C: 125°C; AEC Qualified: No; Peak Reverse Current: 0.02uA; SizeZ_mm: 1.15mm; Max Surge Forward Current: 600mA
D23-D25 = CMP-0002892-3: LED, Yellow, SMD; Manufacturer: Wurth Elektronik; Value1: W; Vf_V: 2V; Type: AlInGaP; Io_A: 20mA
DIT = CMP-0054951-1: Header, 100mil, 3x1, Tin, TH; Manufacturer: TE Connectivity; CNHeader: TRUE; Green_Lifecycle: Active; Green_REACh: Passed; CT: FALSE
Drain_F Drain_M Drain_P Drain_R Gate_ex Gate_F Gate_M Gate_P Gate_R = CMP-0055140-1: Test Point, Miniature, Orange, TH; Manufacturer: Keystone; CNHeader: FALSE; Green_Lifecycle: Active; Green_REACh: Passed; ContactFinish: Silver; CT: TRUE
EMPS TPH/TPL/BT = CMP-0054952-1: Header, 100mil, 2x1, Tin, TH; Manufacturer: TE Connectivity; CNHeader: TRUE; Green_Lifecycle: Active; Green_REACh: Passed; CT: FALSE
GND1-GND3 RTN1-RTN3 VSS1 VSS2 = CMP-0055138-2: Test Point, Miniature, Black, TH; Manufacturer: Keystone Electronics; ContactFinish: Silver; CNHeader: FALSE; Green_Lifecycle: Active; Green_REACh: Passed; CT: TRUE
L7 = CMP-0059863-1: Inductor, Drum Core, Ferrite, 4.7 uH, 6.5 A, 0.023 ohm, SMD; Manufacturer: Cyntec; Isat: 7A @ % inductance drop; Irms: 6.5A @ C rise; Green_Lifecycle: Not Set; SizeAreaWB_mm2: 77.83; DCR_ohm: 23m; Green_REACh: Incomplete; Value: 4.7uH; Imax_A: 6.5A; SizeZ_mm: 5; SizeX_mm: 7.05; SizeY_mm: 6.6; SizeArea_mm2: 46.53; Ind_H: 4.7µH; AEC Category: Q200
L8 = CMP-0064480-2: Inductor, Shielded Drum Core, Ferrite, 47 uH, 6.8 A, 0.0335 ohm, SMD; Manufacturer: Wurth Elektronik; Isat: 7A @ 30% inductance drop; Irms: 6.8A @ 50C rise; Green_Lifecycle: Active; SizeAreaWB_mm2: 410.06; DCR_ohm: 33.5m; Green_REACh: Passed; Value: 47uH; Imax_A: 6.8A; SizeZ_mm: 9.2; SizeX_mm: 18.3; SizeY_mm: 18.2; SizeArea_mm2: 333.06; Ind_H: 47µH; AEC Category: Q200
L9 = CMP-0061681-2: Inductor, Drum Core, Ferrite, 1 mH, 0.1 A, 13.8 ohm, SMD; Manufacturer: Coilcraft; Isat: 0.1A @ 10% inductance drop; Irms: 0.15A @ 15C rise; Green_Lifecycle: Not Set; SizeAreaWB_mm2: 55.47; DCR_ohm: 13.8; Green_REACh: Incomplete; Value: 1mH; Imax_A: 100mA; SizeZ_mm: 2.92; SizeX_mm: 6.6; SizeY_mm: 4.45; Value2: 0.1A; SizeArea_mm2: 29.37; AEC Category: Q200
Q5 Q6 = CMP-0000510-2: Transistor, NPN, 150 V, 1 A, AEC-Q101, SOT-89; Manufacturer: Diodes Inc.; TaMax_C: 150°C; Value2: 300; Value1: 1 A; Vcesat1_V: 200mV; SizeX_mm: 4.1; SizeY_mm: 4.5; TaMin_C: -65°C; IcRated_A: 1A; CompType: BJT; SizeZ_mm: 1.5; AEC Qualified: Y; Value: 150 V; SizeArea_mm2: 18.45; NPN: 1; Vceo_V: 150V; PNP: 0; AEC Category: Q101; SizeAreaWB_mm2: 28.05; U/M: EA
Q7 Q8 = CMP-0001056-1: MOSFET, N-CH, 150 V, 35 A, PQFN08A; Alternate Manufacturer: None; Manufacturer: Fairchild Semiconductor; SizeZ_mm: 1.1; ChType: N; Value2: 33 nC; VdsMax_V: 150V; SizeX_mm: 5; SizeAreaWB_mm2: 56; SizeY_mm: 6; Vgs_V: 20V; QgTyp_nC: 33; Value: 150V; SizeArea_mm2: 30; AEC Category: Q101; IdsMax_A: 35A; U/M: EA
Q9 = CMP-0000056-3: MOSFET, P-CH, -150 V, -3 A, QFN-8; Alternate Manufacturer: None; Manufacturer: Fairchild Semiconductor; ChType: P; VdsMax_V: -150V; AEC Category: Q101; Value2: 6.2 nC; SizeAreaWB_mm2: 18.49; QgTyp_nC: 6.2; Value: -150V; SizeZ_mm: 0.8; ChMode: Enhancement; AEC Qualified: N; IdsMax_A: -3A; SizeX_mm: 3.3; SizeArea_mm2: 10.89; Vgs_V: -30V
Q10 = CMP-0001057-1: MOSFET, N-CH, 150 V, 6.7 A, PQFN08A; Alternate Manufacturer: None; Manufacturer: Fairchild Semiconductor; SizeZ_mm: 1.1; ChType: N; Value2: 36 nC; Value1: 0.02; VdsMax_V: 150V; SizeX_mm: 5; SizeY_mm: 6; Vgs_V: 4V; Value: 150V; Rdson45_ohm: 0.025; SizeArea_mm2: 30; AEC Category: Q101; IdsMax_A: 6.7A; SizeAreaWB_mm2: 56; U/M: EA; QgTyp_nC: 36
Q11 = CMP-0000985-1: MOSFET, N-CH, 100 V, 26 A, PowerPAK SO-8; Alternate Manufacturer: None; Manufacturer: Fairchild Semiconductor; SizeZ_mm: 1.12; ChType: N; Value2: 4.2 nC; Value1: 0.03; VdsMax_V: 100V; SizeX_mm: 5.99; SizeY_mm: 4.9; Vgs_V: 20V; Value: 100V; Rdson45_ohm: 34m; SizeArea_mm2: 29.351; AEC Category: Q101; IdsMax_A: 26A; SizeAreaWB_mm2: 55.131; U/M: EA; QgTyp_nC: 4.2
Q12 = CMP-0000769-1: MOSFET, N-CH, 60 V, 0.17 A, SOT-23; Alternate Manufacturer: None; Manufacturer: Diodes Inc.; SizeZ_mm: 1.1; ChType: N; Value2: 223 nC; Value1: 7; VdsMax_V: 60V; SizeX_mm: 2.5; SizeY_mm: 3; Vgs_V: 20V; Value: 60V; Rdson45_ohm: 7.5; AEC Category: Q101; IdsMax_A: 170mA; SizeAreaWB_mm2: 14; U/M: EA; QgTyp_nC: 223
R23 = CMP-0015944-1: RES, 33 k, 5%, 1 W, AEC-Q200 Grade 0, 2512; Manufacturer: Vishay-Dale; Power_W: 1W; TempCo: 200 ppm/C; Value_Code: 33k0; U/M: EA; Value: 33k; EIA_Code: E24; SizeX_mm: 6.3; SizeY_mm: 3.2; SizeZ_mm: 0.71; SizeArea_mm2: 20.16; AEC Qualified: Y; VDC_V: 500V; AEC Grade: 0; AEC Category: Q200
R24 = CMP-0015978-3: RES, 51, 5%, 1 W, AEC-Q200 Grade 0, 2512; Manufacturer: Vishay-Dale; Power_W: 1W; TempCo: 200 ppm/C; Value_Code: 51R0; Value: 51; EIA_Code: E24; SizeX_mm: 6.3; SizeY_mm: 3.2; SizeZ_mm: 0.71; SizeArea_mm2: 20.16; AEC Qualified: Y; VDC_V: 500V; AEC Grade: 0; AEC Category: Q200
R25 = CMP-0018576-1: RES, 10 k, 5%, 0.25 W, 1206; Manufacturer: Vishay-Dale; Power_W: 250mW; TempCo: 200 ppm/C; Value_Code: 10k0; U/M: EA; Value: 10k; EIA_Code: E24; SizeX_mm: 3.2; SizeY_mm: 1.6; SizeZ_mm: 1.35; Value2: 0.25W; SizeArea_mm2: 5.12; VDC_V: 200V; AEC Category: Q200
R27 = CMP-0018688-2: RES, 4.3 k, 5%, 0.25 W, 1206; Manufacturer: Vishay-Dale; Power_W: 250mW; TempCo: 200 ppm/C; Value_Code: 4k30; U/M: EA; Value: 4.3k; EIA_Code: E24; SizeX_mm: 3.2; SizeY_mm: 1.6; SizeZ_mm: 1.35; Value2: 0.25W; SizeArea_mm2: 5.12; VDC_V: 200V; AEC Category: Q200
R28 = CMP-0016779-2: RES, 20.0 k, 1%, 0.25 W, 1206; Manufacturer: Vishay-Dale; Power_W: 250mW; TempCo: 100 ppm/C; Value_Code: 20k0; U/M: EA; Value: 20.0k; EIA_Code: E96; Res_ohm: 20k; SizeX_mm: 3.2; SizeY_mm: 1.6; SizeZ_mm: 1.35; Value2: 0.25W; SizeArea_mm2: 5.12; VDC_V: 200V; AEC Category: Q200
R29 = CMP-0018659-1: RES, 33, 5%, 0.25 W, 1206; Manufacturer: Vishay-Dale; Power_W: 250mW; TempCo: 200 ppm/C; Value_Code: 33R0; U/M: EA; Value: 33; EIA_Code: E24; SizeX_mm: 3.2; SizeY_mm: 1.6; SizeZ_mm: 1.35; Value2: 0.25W; SizeArea_mm2: 5.12; VDC_V: 200V; AEC Category: Q200
R30 = CMP-0022931-4: RES, 237 k, 1%, 0.1 W, 0603; Manufacturer: Yageo; Power_W: 100mW; TempCo: 100 ppm/C; Value: 237k; EIA_Code: E96; SizeX_mm: 1.6; SizeY_mm: 0.8; SizeZ_mm: 1; Value2: 0.1W; SizeArea_mm2: 1.28; AEC Qualified: N; VDC_V: 75V; AEC Category: Q200; SizeAreaWB_mm2: 4.68
R31 R53 = CMP-0021998-4: RES, 10.0 k, 1%, 0.1 W, AEC-Q200 Grade 0, 0603; Manufacturer: Vishay-Dale; Power_W: 100mW; TempCo: 100 ppm/C; Value_Code: 10k0; Value: 10.0k; EIA_Code: E96; Res_ohm: 10k; SizeX_mm: 1.6; SizeY_mm: 0.8; SizeZ_mm: 1; Value2: 0.1W; SizeArea_mm2: 1.28; AEC Qualified: Y; VDC_V: 75V; AEC Category: Q200; AEC Grade: 0
R32 = CMP-0022532-4: RES, 60.4 k, 1%, 0.1 W, AEC-Q200 Grade 0, 0603; Manufacturer: Vishay-Dale; Power_W: 100mW; TempCo: 100 ppm/C; Value_Code: 60k4; Value: 60.4k; EIA_Code: E96; SizeX_mm: 1.6; SizeY_mm: 0.8; SizeZ_mm: 1; Value2: 0.1W; SizeArea_mm2: 1.28; AEC Qualified: Y; VDC_V: 75V; AEC Category: Q200; AEC Grade: 0
R33 = CMP-0015868-3: RES, 10 k, 5%, 1 W, AEC-Q200 Grade 0, 2512; Manufacturer: Vishay-Dale; Power_W: 1W; TempCo: 200 ppm/C; Value_Code: 10k0; Value: 10k; EIA_Code: E24; SizeX_mm: 6.3; SizeY_mm: 3.2; SizeZ_mm: 0.71; SizeArea_mm2: 20.16; AEC Qualified: Y; VDC_V: 500V; AEC Grade: 0; AEC Category: Q200
R34 R36 = CMP-0025703-4: RES, 10, 5%, 0.1 W, AEC-Q200 Grade 0, 0603; Manufacturer: Vishay-Dale; Power_W: 100mW; TempCo: 200 ppm/C; Value_Code: 10R0; Value: 10; EIA_Code: E24; SizeX_mm: 1.6; SizeY_mm: 0.8; SizeZ_mm: 1; Value2: 0.1W; SizeArea_mm2: 1.28; AEC Qualified: Y; VDC_V: 75V; AEC Category: Q200; AEC Grade: 0
R35 = CMP-0022447-4: RES, 49.9 k, 1%, 0.1 W, AEC-Q200 Grade 0, 0603; Manufacturer: Vishay-Dale; Power_W: 100mW; TempCo: 100 ppm/C; Value_Code: 49k9; Value: 49.9k; EIA_Code: E96; SizeX_mm: 1.6; SizeY_mm: 0.8; SizeZ_mm: 1; Value2: 0.1W; SizeArea_mm2: 1.28; AEC Qualified: Y; VDC_V: 75V; AEC Category: Q200; AEC Grade: 0
R37 = CMP-0023027-4: RES, 31.6, 1%, 0.1 W, 0603; Manufacturer: Yageo; Power_W: 100mW; TempCo: 100 ppm/C; Value_Code: 31R6; Value: 31.6; EIA_Code: E96; SizeX_mm: 1.6; SizeY_mm: 0.8; SizeZ_mm: 1; Value2: 0.1W; SizeArea_mm2: 1.28; AEC Qualified: N; VDC_V: 75V; AEC Category: Q200; SizeAreaWB_mm2: 4.68
R38 = CMP-0023123-5: RES, 45.3, 1%, 0.1 W, 0603; Manufacturer: Yageo; Power_W: 100mW; TempCo: 100 ppm/C; Value_Code: 45R3; Value: 45.3; EIA_Code: E96; SizeX_mm: 1.6; SizeY_mm: 0.8; SizeZ_mm: 1; Value2: 0.1W; SizeArea_mm2: 1.28; AEC Qualified: N; VDC_V: 75V; AEC Category: Q200; SizeAreaWB_mm2: 4.68
R39 = CMP-0082530-1: RES, 100 k, 5%, 0.1 W, 0603; Manufacturer: Vishay-Dale; Power_W: 100mW; TempCo: 200 ppm/C; SizeAreaWB_mm2: 4.68; Value: 100k; EIA_Code: E24; SizeX_mm: 1.6; SizeY_mm: 0.8; SizeZ_mm: 1; Value2: 0.1W; SizeArea_mm2: 1.28; AEC Qualified: N; VDC_V: 75V; AEC Category: Q200
R40 = CMP-0023000-5: RES, 2.00 k, 1%, 0.1 W, 0603; Manufacturer: Yageo; Power_W: 100mW; TempCo: 100 ppm/C; Value_Code: 2k00; Value: 2.00k; EIA_Code: E96; Res_ohm: 2k; SizeX_mm: 1.6; SizeY_mm: 0.8; SizeZ_mm: 1; Value2: 0.1W; SizeArea_mm2: 1.28; AEC Qualified: N; VDC_V: 75V; AEC Category: Q200; SizeAreaWB_mm2: 4.68
R41 = CMP-0022965-5: RES, 27.4 k, 1%, 0.1 W, 0603; Manufacturer: Yageo; Power_W: 100mW; TempCo: 100 ppm/C; Value_Code: 27k4; Value: 27.4k; EIA_Code: E96; SizeX_mm: 1.6; SizeY_mm: 0.8; SizeZ_mm: 1; Value2: 0.1W; SizeArea_mm2: 1.28; AEC Qualified: N; VDC_V: 75V; AEC Category: Q200; SizeAreaWB_mm2: 4.68
R42 = CMP-0017281-2: RES, 0.05, 1%, 1 W, AEC-Q200 Grade 0, 1206; Manufacturer: Panasonic; SizeZ_mm: 1.35; Value2: 1W; SizeArea_mm2: 5.12; AEC Qualified: Y; AEC Grade: 0; AEC Category: Q200; TempCo: 50 ppm/C; Value_Code: R050; U/M: EA; Value: 0.05; EIA_Code: E96; SizeX_mm: 3.2; SizeY_mm: 1.6
R43 = CMP-0022879-5: RES, 1.47 k, 1%, 0.1 W, 0603; Manufacturer: Yageo; Power_W: 100mW; TempCo: 100 ppm/C; Value_Code: 1k47; Value: 1.47k; EIA_Code: E96; SizeX_mm: 1.6; SizeY_mm: 0.8; SizeZ_mm: 1; Value2: 0.1W; SizeArea_mm2: 1.28; AEC Qualified: N; VDC_V: 75V; AEC Category: Q200; SizeAreaWB_mm2: 4.68
R44 R45 = CMP-0022458-2: RES, 4.99 k, 1%, 0.1 W, 0603; Manufacturer: Vishay-Dale; Power_W: 100mW; TempCo: 100 ppm/C; Value_Code: 4k99; U/M: EA; Value: 4.99k; EIA_Code: E96; SizeX_mm: 1.6; SizeY_mm: 0.8; SizeZ_mm: 1; Value2: 0.1W; SizeArea_mm2: 1.28; VDC_V: 75V; AEC Category: Q200
R46 = CMP-0022268-4: RES, 2.00 k, 1%, 0.1 W, AEC-Q200 Grade 0, 0603; Manufacturer: Vishay-Dale; Power_W: 100mW; TempCo: 100 ppm/C; Value_Code: 2k00; Value: 2.00k; EIA_Code: E96; Res_ohm: 2k; SizeX_mm: 1.6; SizeY_mm: 0.8; SizeZ_mm: 1; Value2: 0.1W; SizeArea_mm2: 1.28; AEC Qualified: Y; VDC_V: 75V; AEC Category: Q200; AEC Grade: 0
R47 = CMP-0022410-4: RES, 40.2 k, 1%, 0.1 W, AEC-Q200 Grade 0, 0603; Manufacturer: Vishay-Dale; Power_W: 100mW; TempCo: 100 ppm/C; Value_Code: 40k2; Value: 40.2k; EIA_Code: E96; SizeX_mm: 1.6; SizeY_mm: 0.8; SizeZ_mm: 1; Value2: 0.1W; SizeArea_mm2: 1.28; AEC Qualified: Y; VDC_V: 75V; AEC Category: Q200; AEC Grade: 0
R48 R55 = CMP-0022544-4: RES, 64.9 k, 1%, 0.1 W, AEC-Q200 Grade 0, 0603; Manufacturer: Vishay-Dale; Power_W: 100mW; TempCo: 100 ppm/C; Value_Code: 64k9; Value: 64.9k; EIA_Code: E96; SizeX_mm: 1.6; SizeY_mm: 0.8; SizeZ_mm: 1; Value2: 0.1W; SizeArea_mm2: 1.28; AEC Qualified: Y; VDC_V: 75V; AEC Category: Q200; AEC Grade: 0
R49 = CMP-0022109-5: RES, 1.00 k, 1%, 0.1 W, AEC-Q200 Grade 0, 0603; Manufacturer: Vishay-Dale; Power_W: 100mW; TempCo: 100 ppm/C; Value_Code: 1k00; Value: 1.00k; EIA_Code: E96; Res_ohm: 1k; SizeX_mm: 1.6; SizeY_mm: 0.8; SizeZ_mm: 1; Value2: 0.1W; SizeArea_mm2: 1.28; AEC Qualified: Y; VDC_V: 75V; AEC Category: Q200; AEC Grade: 0
R50 = CMP-0022445-4: RES, 499 k, 1%, 0.1 W, AEC-Q200 Grade 0, 0603; Manufacturer: Vishay-Dale; Power_W: 100mW; TempCo: 100 ppm/C; Value: 499k; EIA_Code: E96; SizeX_mm: 1.6; SizeY_mm: 0.8; SizeZ_mm: 1; Value2: 0.1W; SizeArea_mm2: 1.28; AEC Qualified: Y; VDC_V: 75V; AEC Category: Q200; AEC Grade: 0
R51 = CMP-0022008-4: RES, 110 k, 1%, 0.1 W, AEC-Q200 Grade 0, 0603; Manufacturer: Vishay-Dale; Power_W: 100mW; TempCo: 100 ppm/C; Value: 110k; EIA_Code: E96; SizeX_mm: 1.6; SizeY_mm: 0.8; SizeZ_mm: 1; Value2: 0.1W; SizeArea_mm2: 1.28; AEC Qualified: Y; VDC_V: 75V; AEC Category: Q200; AEC Grade: 0
R52 = CMP-0023151-1: RES, 4.64 k, 1%, 0.1 W, 0603; Manufacturer: Yageo America; Power_W: 100mW; TempCo: 200 ppm/C; Value_Code: 4k64; U/M: EA; Value: 4.64k; EIA_Code: E96; SizeX_mm: 1.6; SizeY_mm: 0.8; SizeZ_mm: 1; Value2: 0.1W; SizeArea_mm2: 1.28; VDC_V: 150V; AEC Category: Q200
R54 = CMP-0021998-4: RES, 10.0 k, 1%, 0.1 W, AEC-Q200 Grade 0, 0603; Manufacturer: Vishay-Dale; CompType: Resistor; Value: 10.0k; Res_ohm: 10k; Value_Code: 10k0; Power_W: 100mW; Value2: 0.1W; VDC_V: 75V; TempCo: 100 ppm/C; SizeArea_mm2: 1.28; SizeX_mm: 1.6; SizeY_mm: 0.8; SizeZ_mm: 1; EIA_Code: E96; AEC Category: Q200; AEC Qualified: Y; AEC Grade: 0
R59 = CMP-0021990-4: RES, 100 k, 1%, 0.1 W, AEC-Q200 Grade 0, 0603; Manufacturer: Vishay-Dale; Power_W: 100mW; TempCo: 100 ppm/C; Value: 100k; EIA_Code: E96; SizeX_mm: 1.6; SizeY_mm: 0.8; SizeZ_mm: 1; Value2: 0.1W; SizeArea_mm2: 1.28; AEC Qualified: Y; VDC_V: 75V; AEC Category: Q200; AEC Grade: 0
R60-R65 = CMP-0025753-1: RES, 20 k, 5%, 0.1 W, 0603; Manufacturer: Vishay-Dale; Power_W: 100mW; TempCo: 200 ppm/C; Value_Code: 20k0; U/M: EA; Value: 20k; EIA_Code: E24; SizeX_mm: 1.6; SizeY_mm: 0.8; SizeZ_mm: 1; Value2: 0.1W; SizeArea_mm2: 1.28; VDC_V: 75V; AEC Category: Q200
R120 = CMP-0017248-2: RES, 0.1, 1%, 0.5 W, 1206; Manufacturer: Bourns; Power_W: 500mW; TempCo: 150 ppm/C; Value_Code: R100; U/M: EA; Value: 0.1; EIA_Code: E96; SizeX_mm: 3.2; SizeY_mm: 1.6; SizeZ_mm: 1.35; Value2: 0.5W; SizeArea_mm2: 5.12; VDC_V: 0V; AEC Category: Q200
R122 = CMP-0020802-2: RES, 0, 5%, 0.125 W, 0805; Manufacturer: Rohm; Power_W: 125mW; TempCo: 400 ppm/C; Value_Code: 0000; U/M: EA; Value: 0; EIA_Code: E24; SizeX_mm: 2; SizeY_mm: 1.25; SizeZ_mm: 1.45; Value2: 0.125W; SizeArea_mm2: 2.5; VDC_V: 150V; AEC Category: Q200
T2 = CMP-0096341-1: TRANSFORMER; Manufacturer: Wurth Electronics; SizeZ_mm: 11.43mm; DCR_ohm: 45m; AEC Qualified: No; Ns1toNp: 1:1; Rsec1_ohm: 40m; Voltage_Isolation_Vrms: 1.5kV; Frequency_Fixed: 250kHz; Ind_H: 100µH
U1 = CMP-0860918-1: TPS23730RMT, RMT0045A (VQFN-45); Alternate Manufacturer: Texas Instruments; SizeArea_mm2: 35; CompType: IC; SizeY_mm: 7; SizeAreaWB_mm2: 63; AEC Category: Q200; SizeZ_mm: 1; AEC Qualified: N; SizeX_mm: 5
U2 = CMP-0006166-3: Optocoupler, 3.75 kV, 80-160% CTR, SMT; Manufacturer: Vishay-Semiconductor; CTR (Max): 160%; SizeAreaWB_mm2: 43.65; CTR (Min): 80%; SizeZ_mm: 2.3; SizeX_mm: 7; SizeY_mm: 2.85; SizeArea_mm2: 19.95; Voltage_Isolation_Vrms: 3.75kV
U3 = CMP-0032888-1: Adjustable Precision Shunt Regulator, 34 ppm / degC, 100 mA, -40 to 85 degC, 5-pin SOT-23 (DBV), Green (RoHS & no Sb/Br); Manufacturer: Texas Instruments; Rating: Military; Initial Accuracy @ 25/deg C(%): 2; Iout/Iz(Max)(mA): 100; Min Iz for Regulation(uA): 600; SubFamily: Shunt Voltage Reference; Temp Coeff(Max)(ppm/ degree C): 92; Temp Coeff(Typ)(ppm/ degree C): 34; VO Adj(Max)(V): 36; VO Adj(Min)(V): 2.495
U4-U7 = CMP-0079530-1: Optocoupler, 3.75 kV, 160-320% CTR, SMT; Manufacturer: Vishay-Semiconductor; CTR (Max): 320%; SizeAreaWB_mm2: 43.65; CTR (Min): 160%; SizeZ_mm: 2.3; SizeX_mm: 7; SizeY_mm: 2.85; SizeArea_mm2: 19.95; Voltage_Isolation_Vrms: 3.75kV
VCC VDD VOUT = CMP-0055137-2: Test Point, Miniature, Red, TH; Manufacturer: Keystone Electronics; Green_REACh: Passed; Green_Lifecycle: Active; ContactFinish: Silver; CNHeader: FALSE; CT: TRUE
